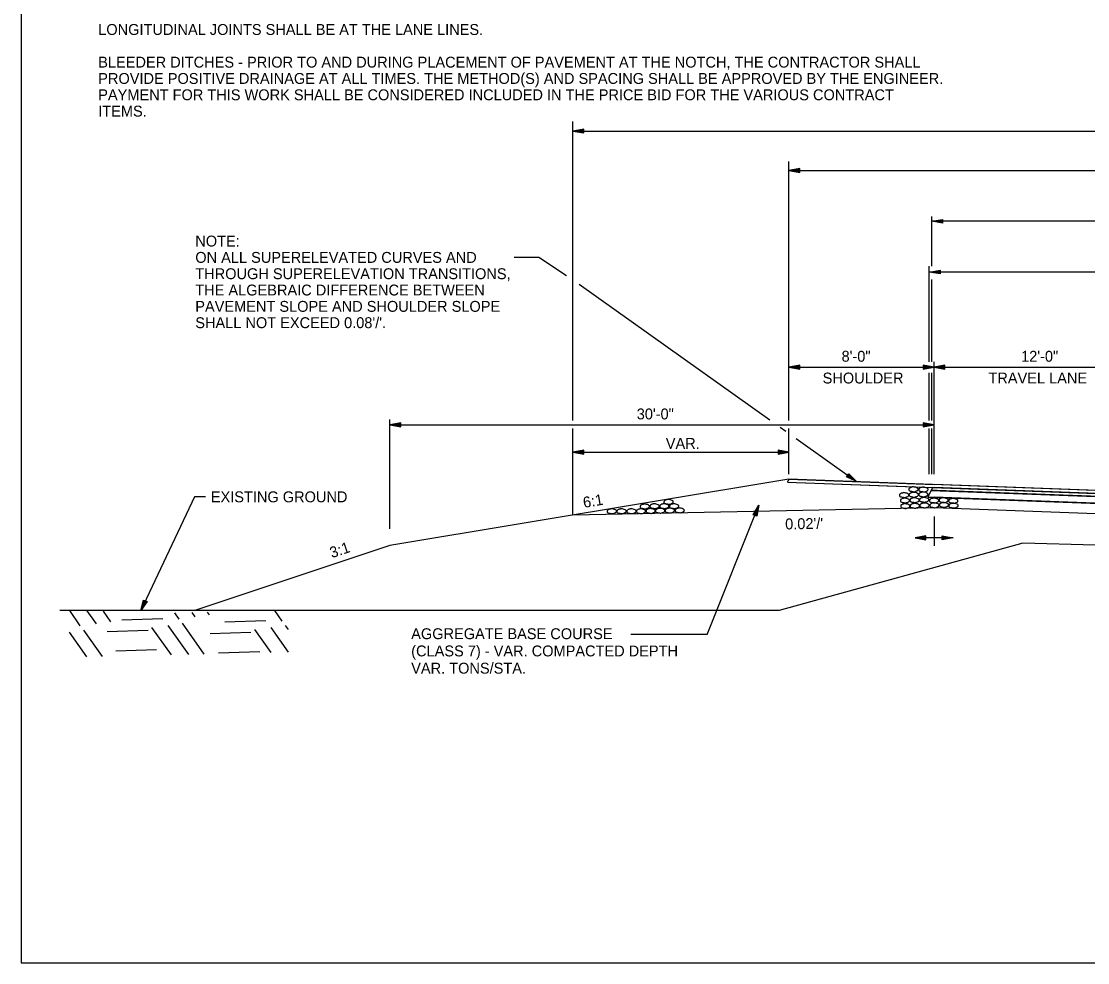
# Model space of a CAD drawing. Extents: x 1461846 to 1462006, y 1686171 to 1686805.
# Drawn here: x 1461846.4 to 1461905.1, y 1686568.7 to 1686620.6 of the extents above; entities that cross this region are included whole.
import ezdxf

# ---------------------------------------------------------------- set-up
doc = ezdxf.new("R2010")
doc.units = 0
for name, color, linetype in [('1', 7, 'Continuous'), ('10', 7, 'Continuous'), ('19', 7, 'Continuous'), ('20', 7, 'Continuous'), ('R_Draft', 7, 'Continuous')]:
    doc.layers.add(name, color=color, linetype=linetype)

# ---------------------------------------------------------------- blocks, each defined once
blk = doc.blocks.new('ROCKS')
at = {"layer": '1'}
blk.add_spline([(0.013, 0.06), (0.053, 0.053), (0.107, 0.033), (0.133, 0.013), (0.133, -0.007), (0.12, -0.033), (0.107, -0.04), (0.073, -0.053), (0.033, -0.067), (0.013, -0.067), (-0.02, -0.06), (-0.06, -0.053), (-0.087, -0.047), (-0.113, -0.02), (-0.113, -0.007), (-0.107, 0.02), (-0.087, 0.033), (-0.067, 0.047), (-0.033, 0.053), (-0.02, 0.06), (0.013, 0.06)], degree=3, dxfattribs=at)

msp = doc.modelspace()

# ---------------------------------------------------------------- linework, layer by layer
at = {"layer": '10'}
for p, q in [((1461846.353, 1686672.939), (1461846.353, 1686568.707)), ((1461846.353, 1686568.707), (1462005.889, 1686568.707))]:
    msp.add_line(p, q, dxfattribs=at)
at = {"layer": '19'}
for p, q in [((1461876.759, 1686598.601), (1461876.759, 1686615.073)), ((1461877.359, 1686614.658), (1461876.759, 1686614.553)), ((1461876.759, 1686614.553), (1461973.451, 1686614.553)), ((1461876.759, 1686614.553), (1461877.359, 1686614.448)), ((1461877.359, 1686614.603), (1461876.919, 1686614.568)), ((1461876.919, 1686614.538), (1461877.359, 1686614.498)), ((1461877.359, 1686614.448), (1461877.359, 1686614.658)), ((1461888.675, 1686599.001), (1461888.675, 1686612.881)), ((1461889.275, 1686612.486), (1461888.675, 1686612.381)), ((1461888.675, 1686612.381), (1461963.675, 1686612.381)), ((1461888.675, 1686612.381), (1461889.275, 1686612.276)), ((1461889.275, 1686612.431), (1461888.835, 1686612.396)), ((1461888.835, 1686612.366), (1461889.275, 1686612.326)), ((1461889.275, 1686612.276), (1461889.275, 1686612.486)), ((1461876.759, 1686593.381), (1461876.759, 1686598.163)), ((1461888.675, 1686595.638), (1461888.675, 1686598.163)), ((1461888.675, 1686595.367), (1461888.593, 1686595.203)), ((1461896.593, 1686594.907), (1461896.327, 1686594.375)), ((1461896.511, 1686594.743), (1461896.327, 1686594.375)), ((1461884.171, 1686586.802), (1461887.023, 1686593.921)), ((1461886.704, 1686593.405), (1461887.023, 1686593.921)), ((1461886.75, 1686593.387), (1461886.949, 1686593.78)), ((1461886.975, 1686593.769), (1461886.849, 1686593.348)), ((1461887.023, 1686593.921), (1461886.897, 1686593.326)), ((1461886.897, 1686593.326), (1461886.704, 1686593.405)), ((1461849.602, 1686587.28), (1461849.02, 1686588.113)), ((1461850.495, 1686587.394), (1461849.99, 1686588.1)), ((1461851.287, 1686587.505), (1461850.881, 1686588.087)), ((1461855.049, 1686587.652), (1461854.815, 1686587.985)), ((1461855.942, 1686587.766), (1461855.77, 1686588.006)), ((1461856.734, 1686587.877), (1461856.625, 1686588.025)), ((1461860.729, 1686587.54), (1461860.323, 1686588.113)), ((1461854.161, 1686587.66), (1461851.901, 1686587.593)), ((1461855.58, 1686585.704), (1461854.448, 1686587.303)), ((1461856.434, 1686585.722), (1461855.241, 1686587.415)), ((1461859.839, 1686587.558), (1461857.581, 1686587.481)), ((1461861.08, 1686587.081), (1461860.92, 1686587.302)), ((1461849.971, 1686585.573), (1461849.002, 1686586.931)), ((1461850.826, 1686585.591), (1461849.794, 1686587.042)), ((1461853.346, 1686587.012), (1461851.077, 1686586.944)), ((1461854.625, 1686585.683), (1461853.556, 1686587.189)), ((1461859.015, 1686586.908), (1461856.757, 1686586.832)), ((1461860.133, 1686585.811), (1461859.235, 1686587.077)), ((1461861.088, 1686585.832), (1461860.128, 1686587.191)), ((1461884.171, 1686586.802), (1461879.961, 1686586.802)), ((1461853.814, 1686585.952), (1461851.556, 1686585.876)), ((1461859.494, 1686585.84), (1461857.224, 1686585.772))]:
    msp.add_line(p, q, dxfattribs=at)
for points in [[(1461888.593, 1686595.203), (1461901.594, 1686594.722), (1461926.175, 1686593.812), (1461955.675, 1686592.721), (1461963.76, 1686592.398), (1461963.675, 1686592.568), (1461955.675, 1686592.888), (1461926.175, 1686593.979), (1461901.548, 1686594.89), (1461888.675, 1686595.367)], [(1461896.511, 1686594.743), (1461907.594, 1686594.333), (1461926.167, 1686593.646), (1461955.902, 1686592.545), (1461963.845, 1686592.227), (1461963.845, 1686592.227), (1461963.76, 1686592.398), (1461963.76, 1686592.398), (1461926.323, 1686593.807), (1461907.548, 1686594.502), (1461896.593, 1686594.907)]]:
    msp.add_lwpolyline(points, close=True, dxfattribs=at)
for points in [[(1461896.327, 1686594.375), (1461896.821, 1686594.357), (1461926.175, 1686593.271), (1461955.675, 1686592.179), (1461964.036, 1686591.845)], [(1461963.845, 1686592.227), (1461955.675, 1686592.554), (1461926.167, 1686593.646), (1461896.842, 1686594.731), (1461896.511, 1686594.743)]]:
    msp.add_lwpolyline(points, dxfattribs=at)
at = {"layer": '20'}
for p, q in [((1461896.55, 1686607.106), (1461896.55, 1686609.836)), ((1461896.55, 1686609.581), (1461897.15, 1686609.686)), ((1461897.15, 1686609.476), (1461896.55, 1686609.581)), ((1461963.8, 1686609.581), (1461896.55, 1686609.581)), ((1461896.71, 1686609.596), (1461897.15, 1686609.631)), ((1461897.15, 1686609.526), (1461896.71, 1686609.566)), ((1461897.15, 1686609.686), (1461897.15, 1686609.476)), ((1461896.413, 1686601.837), (1461896.413, 1686607.106)), ((1461896.413, 1686606.781), (1461897.013, 1686606.886)), ((1461963.934, 1686606.781), (1461896.413, 1686606.781)), ((1461897.013, 1686606.676), (1461896.413, 1686606.781)), ((1461896.573, 1686606.796), (1461897.013, 1686606.831)), ((1461897.013, 1686606.726), (1461896.573, 1686606.766)), ((1461897.013, 1686606.886), (1461897.013, 1686606.676)), ((1461896.55, 1686601.837), (1461896.55, 1686606.376)), ((1461896.413, 1686598.601), (1461896.413, 1686601.222)), ((1461896.55, 1686598.601), (1461896.55, 1686601.222)), ((1461896.413, 1686595.638), (1461896.413, 1686598.163)), ((1461896.55, 1686595.638), (1461896.55, 1686598.163)), ((1461877.359, 1686596.955), (1461876.759, 1686596.85)), ((1461876.759, 1686596.85), (1461888.675, 1686596.85)), ((1461876.759, 1686596.85), (1461877.359, 1686596.745)), ((1461877.359, 1686596.9), (1461876.919, 1686596.865)), ((1461876.919, 1686596.835), (1461877.359, 1686596.795)), ((1461877.359, 1686596.745), (1461877.359, 1686596.955)), ((1461888.075, 1686596.955), (1461888.075, 1686596.745)), ((1461888.675, 1686596.85), (1461888.075, 1686596.955)), ((1461888.515, 1686596.865), (1461888.075, 1686596.9)), ((1461888.075, 1686596.745), (1461888.675, 1686596.85)), ((1461888.075, 1686596.795), (1461888.515, 1686596.835))]:
    msp.add_line(p, q, dxfattribs=at)
at = {"layer": 'R_Draft'}
for p, q in [((1461888.675, 1686598.601), (1461888.675, 1686601.837)), ((1461889.275, 1686601.642), (1461888.675, 1686601.537)), ((1461888.675, 1686601.537), (1461896.675, 1686601.537)), ((1461888.675, 1686601.537), (1461889.275, 1686601.432)), ((1461889.275, 1686601.587), (1461888.835, 1686601.552)), ((1461888.835, 1686601.522), (1461889.275, 1686601.482)), ((1461889.275, 1686601.432), (1461889.275, 1686601.642)), ((1461896.075, 1686601.642), (1461896.075, 1686601.432)), ((1461896.675, 1686601.537), (1461896.075, 1686601.642)), ((1461896.515, 1686601.552), (1461896.075, 1686601.587)), ((1461896.075, 1686601.432), (1461896.675, 1686601.537)), ((1461896.075, 1686601.482), (1461896.515, 1686601.522)), ((1461896.675, 1686595.638), (1461896.675, 1686601.837)), ((1461897.275, 1686601.642), (1461896.675, 1686601.537)), ((1461896.675, 1686601.537), (1461908.675, 1686601.537)), ((1461896.675, 1686601.537), (1461897.275, 1686601.432)), ((1461897.275, 1686601.587), (1461896.835, 1686601.552)), ((1461896.835, 1686601.522), (1461897.275, 1686601.482)), ((1461897.275, 1686601.432), (1461897.275, 1686601.642)), ((1461866.675, 1686592.615), (1461866.675, 1686598.658)), ((1461867.275, 1686598.463), (1461866.675, 1686598.358)), ((1461867.275, 1686598.408), (1461866.835, 1686598.373)), ((1461867.275, 1686598.253), (1461867.275, 1686598.463)), ((1461896.075, 1686598.463), (1461896.075, 1686598.253)), ((1461896.675, 1686598.358), (1461896.075, 1686598.463)), ((1461896.515, 1686598.373), (1461896.075, 1686598.408)), ((1461866.675, 1686598.358), (1461896.675, 1686598.358)), ((1461866.675, 1686598.358), (1461867.275, 1686598.253)), ((1461866.835, 1686598.343), (1461867.275, 1686598.303)), ((1461888.675, 1686595.638), (1461888.675, 1686598.058)), ((1461896.075, 1686598.253), (1461896.675, 1686598.358)), ((1461896.075, 1686598.303), (1461896.515, 1686598.343)), ((1461891.857, 1686595.492), (1461891.979, 1686595.663)), ((1461892.406, 1686595.229), (1461891.857, 1686595.492)), ((1461892.267, 1686595.309), (1461891.886, 1686595.533)), ((1461891.947, 1686595.618), (1461892.284, 1686595.334)), ((1461891.979, 1686595.663), (1461892.406, 1686595.229)), ((1461888.675, 1686595.367), (1461866.675, 1686591.7)), ((1461888.593, 1686595.203), (1461896.675, 1686594.904)), ((1461888.675, 1686595.367), (1461896.675, 1686595.071)), ((1461896.327, 1686594.375), (1461896.675, 1686594.362)), ((1461896.511, 1686594.743), (1461896.675, 1686594.737)), ((1461896.675, 1686593.779), (1461876.759, 1686593.381)), ((1461896.675, 1686593.311), (1461896.675, 1686591.678)), ((1461896.227, 1686592.235), (1461895.627, 1686592.13)), ((1461895.627, 1686592.13), (1461896.227, 1686592.025)), ((1461897.723, 1686592.13), (1461895.627, 1686592.13)), ((1461896.227, 1686592.18), (1461895.787, 1686592.145)), ((1461895.787, 1686592.115), (1461896.227, 1686592.075)), ((1461896.227, 1686592.025), (1461896.227, 1686592.235)), ((1461897.123, 1686592.025), (1461897.123, 1686592.235)), ((1461897.123, 1686592.235), (1461897.723, 1686592.13)), ((1461897.123, 1686592.18), (1461897.563, 1686592.145)), ((1461897.723, 1686592.13), (1461897.123, 1686592.025)), ((1461897.563, 1686592.115), (1461897.123, 1686592.075)), ((1461866.675, 1686591.7), (1461855.915, 1686588.113)), ((1461852.934, 1686588.113), (1461853.096, 1686588.7)), ((1461853.285, 1686588.61), (1461852.934, 1686588.113)), ((1461852.993, 1686588.261), (1461853.143, 1686588.673)), ((1461853.242, 1686588.627), (1461853.016, 1686588.252)), ((1461853.096, 1686588.7), (1461853.285, 1686588.61)), ((1461888.135, 1686588.113), (1461848.483, 1686588.113))]:
    msp.add_line(p, q, dxfattribs=at)
for points in [[(1461873.522, 1686607.604), (1461874.885, 1686607.604), (1461876.409, 1686606.586)], [(1461877.107, 1686606.12), (1461887.617, 1686598.638)], [(1461888.196, 1686598.226), (1461888.505, 1686598.006)], [(1461889.078, 1686597.597), (1461892.406, 1686595.229)], [(1461955.675, 1686592.888), (1461926.175, 1686593.979), (1461896.675, 1686595.071)], [(1461955.675, 1686592.721), (1461926.175, 1686593.812), (1461896.675, 1686594.904)], [(1461856.5, 1686594.386), (1461855.9, 1686594.386), (1461852.934, 1686588.113)], [(1461955.675, 1686592.554), (1461926.175, 1686593.646), (1461896.675, 1686594.737)], [(1461955.675, 1686592.179), (1461926.175, 1686593.271), (1461896.675, 1686594.362)], [(1461973.451, 1686590.938), (1461896.675, 1686593.779)], [(1462006.432, 1686592.29), (1461984.037, 1686591.864), (1461966.185, 1686586.988), (1461964.051, 1686586.833), (1461959.64, 1686586.966), (1461951.759, 1686587.197), (1461933.565, 1686590.624), (1461929.565, 1686590.895), (1461917.565, 1686591.309), (1461905.565, 1686591.722), (1461901.565, 1686591.841), (1461888.135, 1686588.113)]]:
    msp.add_lwpolyline(points, dxfattribs=at)

# ---------------------------------------------------------------- block references
at = {"layer": '19', "xscale": 2.061136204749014, "yscale": 2.061136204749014}
for p in [(1461895.519, 1686594.807), (1461896.071, 1686594.798), (1461895.008, 1686594.49), (1461895.054, 1686594.193), (1461895.536, 1686594.51), (1461895.583, 1686594.212), (1461896.066, 1686594.529), (1461896.112, 1686594.231), (1461896.657, 1686594.191), (1461897.185, 1686594.21), (1461897.715, 1686594.172), (1461878.889, 1686593.601), (1461879.427, 1686593.601), (1461879.971, 1686593.601), (1461880.498, 1686593.601), (1461880.706, 1686593.865), (1461881.029, 1686593.616), (1461881.248, 1686593.881), (1461881.553, 1686593.629), (1461881.782, 1686593.881), (1461882.019, 1686594.119), (1461882.087, 1686593.639), (1461882.324, 1686593.881), (1461882.632, 1686593.648), (1461895.071, 1686593.883), (1461895.6, 1686593.902), (1461896.129, 1686593.921), (1461896.674, 1686593.929), (1461897.202, 1686593.948), (1461897.732, 1686593.911)]:
    msp.add_blockref('ROCKS', p, dxfattribs=at)

# ---------------------------------------------------------------- texts
at = {"layer": '19'}
for s, p in [('AGGREGATE BASE COURSE', (1461867.849, 1686586.542)), ('(CLASS 7) - VAR. COMPACTED DEPTH', (1461867.849, 1686585.592)), ('VAR. TONS/STA.', (1461867.849, 1686584.642))]:
    msp.add_text(s, height=0.6, rotation=360, dxfattribs=at).set_placement(p)
at = {"layer": 'R_Draft'}
for s, p in [('LONGITUDINAL JOINTS SHALL BE AT THE LANE LINES.', (1461850.593, 1686619.852)), ('BLEEDER DITCHES - PRIOR TO AND DURING PLACEMENT OF PAVEMENT AT THE NOTCH, THE CONTRACTOR SHALL ', (1461850.593, 1686618.052)), ('PROVIDE POSITIVE DRAINAGE AT ALL TIMES. THE METHOD(S) AND SPACING SHALL BE APPROVED BY THE ENGINEER. ', (1461850.593, 1686617.152)), ('PAYMENT FOR THIS WORK SHALL BE CONSIDERED INCLUDED IN THE PRICE BID FOR THE VARIOUS CONTRACT ', (1461850.593, 1686616.252)), ('ITEMS.', (1461850.593, 1686615.352)), ('NOTE:', (1461855.944, 1686608.188)), ('ON ALL SUPERELEVATED CURVES AND', (1461855.944, 1686607.288)), ('THROUGH SUPERELEVATION TRANSITIONS,', (1461855.944, 1686606.388)), ('THE ALGEBRAIC DIFFERENCE BETWEEN', (1461855.944, 1686605.488)), ('PAVEMENT SLOPE AND SHOULDER SLOPE', (1461855.944, 1686604.588)), ("SHALL NOT EXCEED 0.08'/'.", (1461855.944, 1686603.688)), ('8\'-0"', (1461891.577, 1686601.837)), ('12\'-0"', (1461901.477, 1686601.837)), ('SHOULDER', (1461890.533, 1686600.637)), ('TRAVEL LANE', (1461899.675, 1686600.637)), ('30\'-0"', (1461880.284, 1686598.658)), ('EXISTING GROUND', (1461856.8, 1686594.087))]:
    msp.add_text(s, height=0.6, dxfattribs=at).set_placement(p)
for s, rotation, p in [('VAR.', 360, (1461881.886, 1686597.033)), ('6:1', 9.48253, (1461877.373, 1686593.775)), ("0.02'/'", 1.14576, (1461888.473, 1686592.589)), ('3:1', 18.43495, (1461863.472, 1686591.004))]:
    msp.add_text(s, height=0.6, rotation=rotation, dxfattribs=at).set_placement(p)

doc.saveas('drawing.dxf')
